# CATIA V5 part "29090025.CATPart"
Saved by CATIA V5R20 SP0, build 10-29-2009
Part number: 29090025
Definition: NONE
Nomenclature: 29090025
Source: Unknown
Description: 29090025
Bounding box of the stored display mesh (mm): x -12.5 to 44.548, y -59 to 93.548, z -49 to 49
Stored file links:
  C:\Users\Utente\Desktop\IO LAVORO\3D X SITO CF\X SITO\PLASTICA\RF1\29090025.CATPart
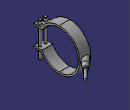
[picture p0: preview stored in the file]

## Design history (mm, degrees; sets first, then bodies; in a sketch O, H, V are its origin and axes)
Body1 "29090025" (main body)
  Solid1: solid without history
